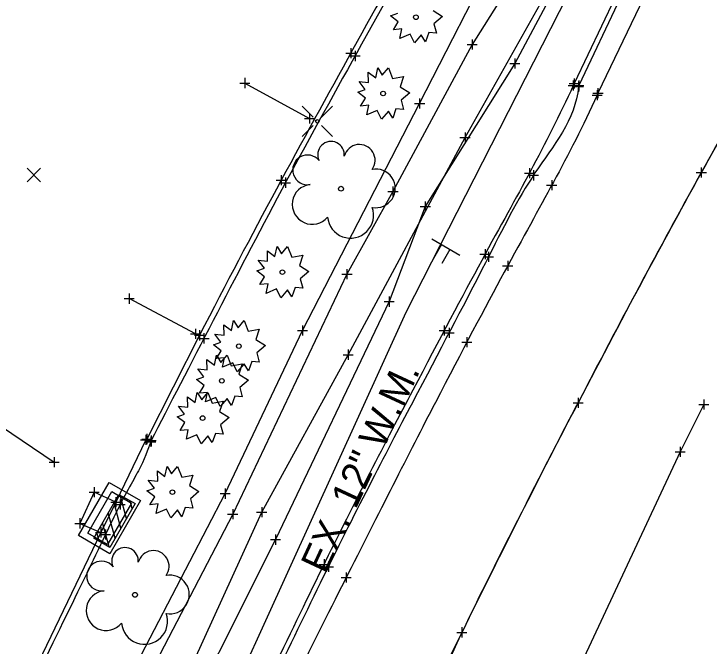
# Model space of a CAD drawing. Extents: x 1324089 to 1329959, y 459099 to 462017.
# Drawn here: x 1324763.5 to 1324832.3, y 459613.2 to 459675.8 of the extents above; entities that cross this region are included whole.
import ezdxf

# ---------------------------------------------------------------- set-up
doc = ezdxf.new("R2010")
doc.units = 0
for name, color, linetype in [('DR_X_Cells', 7, 'Continuous'), ('GK_Drainage_Nodes', 7, 'Continuous'), ('PM_X_Channelizing_Line', 7, 'Continuous'), ('PM_X_CL_Double_Solid', 7, 'Continuous'), ('PM_X_Parking_Lot_Stall', 7, 'Continuous'), ('PM_X_Surveyed_Line', 7, 'Continuous'), ('PV_X_Curb', 7, 'Continuous'), ('PV_X_EOP', 7, 'Continuous'), ('SN_X_Public', 7, 'Continuous'), ('SV_P_Control_Cells_Set', 7, 'Continuous'), ('SV_X_Break_Lines', 7, 'Continuous'), ('SV_X_Random_Point', 7, 'Continuous'), ('SV_X_Shot_Marker', 7, 'Continuous'), ('UT_X_Electric', 7, 'Continuous'), ('UT_X_Telecom', 7, 'Continuous'), ('UT_X_Water', 7, 'Continuous'), ('UT_X_Water_Text', 7, 'Continuous'), ('VG_X_Cells', 7, 'Continuous'), ('VG_X_Flower_Bed', 7, 'Continuous')]:
    doc.layers.add(name, color=color, linetype=linetype)

msp = doc.modelspace()

# ---------------------------------------------------------------- linework, layer by layer
at = {"layer": 'DR_X_Cells'}
for p, q in [((1324774.619, 459625.879), (1324773.998, 459628.183)), ((1324774.054, 459624.901), (1324773.381, 459627.401)), ((1324775.184, 459626.858), (1324774.979, 459627.617)), ((1324773.489, 459623.923), (1324772.816, 459626.423)), ((1324772.897, 459623.046), (1324772.251, 459625.444)), ((1324771.916, 459623.612), (1324771.686, 459624.466))]:
    msp.add_line(p, q, dxfattribs=at)
for points in [[(1324769.875, 459624.165), (1324772.917, 459629.433), (1324776.021, 459627.641), (1324772.979, 459622.373)], [(1324770.787, 459624.408), (1324773.162, 459628.522), (1324775.11, 459627.397), (1324772.735, 459623.283)], [(1324771.374, 459623.925), (1324773.874, 459628.255), (1324775.461, 459627.339), (1324772.961, 459623.008)]]:
    msp.add_lwpolyline(points, close=True, dxfattribs=at)
at = {"layer": 'GK_Drainage_Nodes'}
for p, q in [((1324774.136, 459627.96), (1324774.136, 459627.96)), ((1324771.397, 459626.799), (1324771.397, 459626.799)), ((1324771.974, 459626.465), (1324771.974, 459626.465)), ((1324772.624, 459626.09), (1324772.624, 459626.09)), ((1324772.624, 459626.09), (1324772.624, 459626.09)), ((1324772.948, 459625.903), (1324772.948, 459625.903)), ((1324773.923, 459625.34), (1324773.923, 459625.34)), ((1324774.5, 459625.007), (1324774.5, 459625.007)), ((1324771.761, 459623.846), (1324771.761, 459623.846))]:
    msp.add_line(p, q, dxfattribs=at)
at = {"layer": 'PM_X_Channelizing_Line'}
for p, q in [((1324831.798, 459637.163), (1324829.475, 459632.455)), ((1324829.475, 459632.455), (1324818.676, 459609.429))]:
    msp.add_line(p, q, dxfattribs=at)
for centre, radius, start, end in [((1325573.528, 459249.067), 848.223, 149.963008, 151.013497), ((1325513.668, 459282.23), 779.791, 151.013497, 151.826405), ((1326054.876, 458992.357), 1393.74, 151.826405, 152.434453), ((1325878.632, 459084.361), 1194.926, 152.434453, 153.153503), ((1325333.948, 459360.055), 584.444, 153.153503, 154.181664), ((1324858.545, 459590.062), 56.324, 154.18166, 155.38932), ((1344288.914, 450689.762), 21428.141, 155.389318, 155.4512321)]:
    msp.add_arc(centre, radius, start, end, dxfattribs=at)
at = {"layer": 'PM_X_CL_Double_Solid'}
msp.add_arc((1325531.441, 459274.948), 775.354, 153.934546, 154.866062, dxfattribs=at)
at = {"layer": 'PM_X_Parking_Lot_Stall'}
for p, q in [((1324786.344, 459668.982), (1324792.745, 459665.473)), ((1324781.461, 459644.15), (1324774.879, 459647.636))]:
    msp.add_line(p, q, dxfattribs=at)
at = {"layer": 'PM_X_Surveyed_Line'}
for p, q in [((1324831.798, 459637.163), (1324829.475, 459632.455)), ((1324829.475, 459632.455), (1324818.676, 459609.429))]:
    msp.add_line(p, q, dxfattribs=at)
for points in [[(1324786.344, 459668.982), (1324792.745, 459665.473)], [(1324781.461, 459644.15), (1324774.879, 459647.636)]]:
    msp.add_lwpolyline(points, dxfattribs=at)
for points in [[(1324902.004, 459768.599), (1324894.941, 459763.504), (1324888.122, 459746.257), (1324874.941, 459731.791), (1324865.637, 459716.437), (1324856.475, 459701.876), (1324843.996, 459681.95), (1324831.428, 459660.191), (1324819.333, 459637.476), (1324807.917, 459614.981), (1324797.326, 459592.73), (1324792.039, 459577.402), (1324788.306, 459570.294)], [(1324882.051, 459697.431), (1324879.878, 459695.477), (1324875.317, 459685.045), (1324863.849, 459669.9), (1324852.044, 459648.528), (1324840.309, 459626.835), (1324829.616, 459604.568), (1324819.173, 459582.508), (1324814.023, 459567.354), (1324810.553, 459560.343)], [(1324895.398, 459696.784), (1324891.217, 459693.874), (1324886.406, 459680.591), (1324874.119, 459663.845), (1324862.634, 459642.513), (1324851.351, 459621.014), (1324840.499, 459599.29), (1324829.569, 459576.032), (1324822.647, 459560.039), (1324819.018, 459551.27)]]:
    msp.add_open_spline(points, degree=3, dxfattribs=at)
at = {"layer": 'PV_X_Curb'}
for p, q in [((1324829.782, 459691.74), (1324818.975, 459668.938)), ((1324830.176, 459691.43), (1324819.412, 459668.743)), ((1324818.975, 459668.938), (1324818.877, 459668.729)), ((1324819.412, 459668.743), (1324819.401, 459668.627))]:
    msp.add_line(p, q, dxfattribs=at)
for points in [[(1324817.796, 459706.566), (1324815.952, 459703.677), (1324811.609, 459696.727), (1324804.78, 459685.077), (1324797.497, 459672.141), (1324789.824, 459658.239), (1324783.217, 459645.473), (1324778.794, 459636.954), (1324777.054, 459633.576)], [(1324818.877, 459668.729), (1324817.51, 459665.803), (1324814.677, 459660.19), (1324810.196, 459652.226), (1324803.358, 459639.344), (1324794.246, 459621.807), (1324783.589, 459599.084), (1324776.054, 459584.39), (1324773.333, 459576.628)], [(1324819.401, 459668.627), (1324819.105, 459665.356), (1324814.629, 459660.122), (1324810.65, 459651.989), (1324803.829, 459639.044), (1324794.695, 459621.586), (1324783.937, 459598.887), (1324776.771, 459584.078), (1324773.747, 459576.435)], [(1324777.054, 459633.576), (1324777.041, 459633.536), (1324776.327, 459631.307), (1324774.445, 459628.358), (1324770.667, 459620.305), (1324767.716, 459614.392), (1324765.326, 459609.444)]]:
    msp.add_open_spline(points, degree=3, dxfattribs=at)
at = {"layer": 'PV_X_EOP'}
for p, q in [((1324832.047, 459690.408), (1324821.323, 459667.983)), ((1324821.323, 459667.983), (1324821.233, 459667.781)), ((1324781.846, 459644.003), (1324776.628, 459633.733)), ((1324776.519, 459633.645), (1324773.569, 459627.484)), ((1324776.628, 459633.733), (1324776.519, 459633.645)), ((1324773.569, 459627.484), (1324772.064, 459624.492)), ((1324772.064, 459624.492), (1324764.934, 459609.672))]:
    msp.add_line(p, q, dxfattribs=at)
for points in [[(1324817.184, 459706.405), (1324815.465, 459703.707), (1324811.035, 459696.861), (1324804.312, 459685.413), (1324797.096, 459672.405), (1324789.428, 459658.502), (1324784.502, 459649.145), (1324781.846, 459644.003)], [(1324821.233, 459667.781), (1324819.873, 459664.74), (1324816.914, 459659.104), (1324812.44, 459651.05), (1324805.564, 459638.152), (1324796.645, 459620.538), (1324785.298, 459598.094), (1324779.342, 459582.724), (1324775.523, 459575.408)]]:
    msp.add_open_spline(points, degree=3, dxfattribs=at)
at = {"layer": 'SN_X_Public'}
for p, q in [((1324804.862, 459653.542), (1324807.633, 459651.942)), ((1324805.832, 459652.982), (1324805.032, 459651.597)), ((1324806.663, 459652.502), (1324805.863, 459651.117)), ((1324806.247, 459652.742), (1324806.247, 459652.742))]:
    msp.add_line(p, q, dxfattribs=at)
at = {"layer": 'SV_P_Control_Cells_Set'}
for p, q in [((1324793.112, 459665.607), (1324792.019, 459666.699)), ((1324793.944, 459665.607), (1324795.037, 459666.699)), ((1324792.019, 459663.68), (1324793.112, 459664.774)), ((1324795.037, 459663.68), (1324793.944, 459664.774))]:
    msp.add_line(p, q, dxfattribs=at)
msp.add_circle((1324793.522, 459665.19), 0.17, dxfattribs=at)
at = {"layer": 'SV_X_Break_Lines'}
for points in [[(1324830.664, 459710.011), (1324831.232, 459705.696), (1324825.964, 459694.744), (1324819.943, 459683.777), (1324813.087, 459670.907), (1324804.221, 459656.761), (1324800.65, 459647.335), (1324789.388, 459623.769), (1324778.115, 459601.349)], [(1324754.738, 459640.021), (1324767.463, 459631.432)], [(1324773.569, 459627.484), (1324771.424, 459628.467), (1324770.012, 459625.385), (1324772.064, 459624.492)]]:
    msp.add_lwpolyline(points, dxfattribs=at)
at = {"layer": 'SV_X_Random_Point'}
for p, q in [((1324764.772, 459659.205), (1324766.105, 459660.54)), ((1324764.772, 459660.54), (1324766.105, 459659.205))]:
    msp.add_line(p, q, dxfattribs=at)
at = {"layer": 'SV_X_Shot_Marker'}
for p, q in [((1324808.867, 459673.303), (1324808.867, 459672.303)), ((1324796.851, 459672.449), (1324796.851, 459671.449)), ((1324797.254, 459672.162), (1324797.254, 459671.162)), ((1324808.367, 459672.803), (1324809.367, 459672.803)), ((1324808.867, 459672.803), (1324808.867, 459672.803)), ((1324796.351, 459671.949), (1324797.351, 459671.949)), ((1324796.754, 459671.662), (1324797.754, 459671.662)), ((1324796.851, 459671.949), (1324796.851, 459671.949)), ((1324797.254, 459671.662), (1324797.254, 459671.662)), ((1324812.587, 459670.907), (1324813.587, 459670.907)), ((1324813.087, 459671.407), (1324813.087, 459670.407)), ((1324813.087, 459670.907), (1324813.087, 459670.907)), ((1324786.344, 459669.482), (1324786.344, 459668.482)), ((1324818.975, 459669.438), (1324818.975, 459668.438)), ((1324785.844, 459668.982), (1324786.844, 459668.982)), ((1324786.344, 459668.982), (1324786.344, 459668.982)), ((1324818.377, 459668.729), (1324819.377, 459668.729)), ((1324818.475, 459668.938), (1324819.475, 459668.938)), ((1324818.877, 459669.229), (1324818.877, 459668.229)), ((1324818.877, 459668.729), (1324818.877, 459668.729)), ((1324818.912, 459668.743), (1324819.912, 459668.743)), ((1324818.975, 459668.938), (1324818.975, 459668.938)), ((1324819.401, 459669.127), (1324819.401, 459668.127)), ((1324819.412, 459669.243), (1324819.412, 459668.243)), ((1324819.412, 459668.743), (1324819.412, 459668.743)), ((1324818.901, 459668.627), (1324819.901, 459668.627)), ((1324819.401, 459668.627), (1324819.401, 459668.627)), ((1324821.233, 459668.281), (1324821.233, 459667.281)), ((1324821.323, 459668.483), (1324821.323, 459667.483)), ((1324803.656, 459667.451), (1324803.656, 459666.451)), ((1324820.733, 459667.781), (1324821.733, 459667.781)), ((1324820.823, 459667.983), (1324821.823, 459667.983)), ((1324821.233, 459667.781), (1324821.233, 459667.781)), ((1324821.323, 459667.983), (1324821.323, 459667.983)), ((1324803.156, 459666.951), (1324804.156, 459666.951)), ((1324803.656, 459666.951), (1324803.656, 459666.951)), ((1324792.745, 459665.973), (1324792.745, 459664.973)), ((1324792.245, 459665.473), (1324793.245, 459665.473)), ((1324792.745, 459665.473), (1324792.745, 459665.473)), ((1324808.155, 459664.074), (1324808.155, 459663.074)), ((1324807.655, 459663.574), (1324808.655, 459663.574)), ((1324808.155, 459663.574), (1324808.155, 459663.574)), ((1324814.531, 459660.567), (1324814.531, 459659.567)), ((1324831.558, 459660.619), (1324831.558, 459659.619)), ((1324789.948, 459659.856), (1324789.948, 459658.856)), ((1324814.031, 459660.067), (1324815.031, 459660.067)), ((1324814.442, 459659.845), (1324815.442, 459659.845)), ((1324814.531, 459660.067), (1324814.531, 459660.067)), ((1324814.942, 459660.345), (1324814.942, 459659.345)), ((1324814.942, 459659.845), (1324814.942, 459659.845)), ((1324831.058, 459660.119), (1324832.058, 459660.119)), ((1324831.558, 459660.119), (1324831.558, 459660.119)), ((1324789.448, 459659.356), (1324790.448, 459659.356)), ((1324789.872, 459659.113), (1324790.872, 459659.113)), ((1324789.948, 459659.356), (1324789.948, 459659.356)), ((1324790.372, 459659.613), (1324790.372, 459658.613)), ((1324790.372, 459659.113), (1324790.372, 459659.113)), ((1324816.739, 459659.36), (1324816.739, 459658.36)), ((1324801.014, 459658.752), (1324801.014, 459657.752)), ((1324816.239, 459658.86), (1324817.239, 459658.86)), ((1324816.739, 459658.86), (1324816.739, 459658.86)), ((1324800.514, 459658.252), (1324801.514, 459658.252)), ((1324801.014, 459658.252), (1324801.014, 459658.252)), ((1324804.221, 459657.261), (1324804.221, 459656.261)), ((1324803.721, 459656.761), (1324804.721, 459656.761)), ((1324804.221, 459656.761), (1324804.221, 459656.761)), ((1324810.133, 459652.536), (1324810.133, 459651.536)), ((1324810.487, 459652.265), (1324810.487, 459651.265)), ((1324809.633, 459652.036), (1324810.633, 459652.036)), ((1324809.987, 459651.765), (1324810.987, 459651.765)), ((1324810.133, 459652.036), (1324810.133, 459652.036)), ((1324810.487, 459651.765), (1324810.487, 459651.765)), ((1324811.879, 459650.885), (1324812.879, 459650.885)), ((1324812.379, 459651.385), (1324812.379, 459650.385)), ((1324812.379, 459650.885), (1324812.379, 459650.885)), ((1324796.461, 459650.561), (1324796.461, 459649.561)), ((1324795.961, 459650.061), (1324796.961, 459650.061)), ((1324796.461, 459650.061), (1324796.461, 459650.061)), ((1324774.879, 459648.136), (1324774.879, 459647.136)), ((1324774.379, 459647.636), (1324775.379, 459647.636)), ((1324774.879, 459647.636), (1324774.879, 459647.636)), ((1324800.65, 459647.835), (1324800.65, 459646.835)), ((1324800.15, 459647.335), (1324801.15, 459647.335)), ((1324800.65, 459647.335), (1324800.65, 459647.335)), ((1324781.461, 459644.65), (1324781.461, 459643.65)), ((1324792.042, 459644.978), (1324792.042, 459643.978)), ((1324806.093, 459644.984), (1324806.093, 459643.984)), ((1324806.571, 459644.743), (1324806.571, 459643.743)), ((1324780.961, 459644.15), (1324781.961, 459644.15)), ((1324781.346, 459644.003), (1324782.346, 459644.003)), ((1324781.461, 459644.15), (1324781.461, 459644.15)), ((1324781.846, 459644.503), (1324781.846, 459643.503)), ((1324781.846, 459644.003), (1324781.846, 459644.003)), ((1324782.294, 459644.201), (1324782.294, 459643.201)), ((1324791.542, 459644.478), (1324792.542, 459644.478)), ((1324792.042, 459644.478), (1324792.042, 459644.478)), ((1324805.593, 459644.484), (1324806.593, 459644.484)), ((1324806.071, 459644.243), (1324807.071, 459644.243)), ((1324806.093, 459644.484), (1324806.093, 459644.484)), ((1324806.571, 459644.243), (1324806.571, 459644.243)), ((1324781.794, 459643.701), (1324782.794, 459643.701)), ((1324782.294, 459643.701), (1324782.294, 459643.701)), ((1324807.84, 459643.329), (1324808.84, 459643.329)), ((1324808.34, 459643.829), (1324808.34, 459642.829)), ((1324808.34, 459643.329), (1324808.34, 459643.329)), ((1324796.566, 459642.584), (1324796.566, 459641.584)), ((1324796.066, 459642.084), (1324797.066, 459642.084)), ((1324796.566, 459642.084), (1324796.566, 459642.084)), ((1324819.351, 459637.828), (1324819.351, 459636.828)), ((1324818.851, 459637.328), (1324819.851, 459637.328)), ((1324819.351, 459637.328), (1324819.351, 459637.328)), ((1324831.298, 459637.163), (1324832.298, 459637.163)), ((1324831.798, 459637.663), (1324831.798, 459636.663)), ((1324831.798, 459637.163), (1324831.798, 459637.163)), ((1324776.019, 459633.645), (1324777.019, 459633.645)), ((1324776.128, 459633.733), (1324777.128, 459633.733)), ((1324776.519, 459634.145), (1324776.519, 459633.145)), ((1324776.519, 459633.645), (1324776.519, 459633.645)), ((1324776.554, 459633.576), (1324777.554, 459633.576)), ((1324776.628, 459634.233), (1324776.628, 459633.233)), ((1324776.628, 459633.733), (1324776.628, 459633.733)), ((1324777.015, 459633.956), (1324777.015, 459632.956)), ((1324777.054, 459634.076), (1324777.054, 459633.076)), ((1324777.054, 459633.576), (1324777.054, 459633.576)), ((1324776.515, 459633.456), (1324777.515, 459633.456)), ((1324777.015, 459633.456), (1324777.015, 459633.456)), ((1324829.475, 459632.955), (1324829.475, 459631.955)), ((1324828.975, 459632.455), (1324829.975, 459632.455)), ((1324829.475, 459632.455), (1324829.475, 459632.455)), ((1324767.463, 459631.932), (1324767.463, 459630.932)), ((1324766.963, 459631.432), (1324767.963, 459631.432)), ((1324767.463, 459631.432), (1324767.463, 459631.432)), ((1324771.424, 459628.967), (1324771.424, 459627.967)), ((1324784.385, 459628.824), (1324784.385, 459627.824)), ((1324770.924, 459628.467), (1324771.924, 459628.467)), ((1324771.424, 459628.467), (1324771.424, 459628.467)), ((1324783.885, 459628.324), (1324784.885, 459628.324)), ((1324784.385, 459628.324), (1324784.385, 459628.324)), ((1324773.069, 459627.484), (1324774.069, 459627.484)), ((1324773.069, 459627.484), (1324774.069, 459627.484)), ((1324773.569, 459627.984), (1324773.569, 459626.984)), ((1324773.569, 459627.984), (1324773.569, 459626.984)), ((1324773.569, 459627.484), (1324773.569, 459627.484)), ((1324773.569, 459627.484), (1324773.569, 459627.484)), ((1324773.982, 459627.761), (1324773.982, 459626.761)), ((1324773.482, 459627.261), (1324774.482, 459627.261)), ((1324773.982, 459627.261), (1324773.982, 459627.261)), ((1324785.136, 459626.801), (1324785.136, 459625.801)), ((1324788.009, 459627.003), (1324788.009, 459626.003)), ((1324784.636, 459626.301), (1324785.636, 459626.301)), ((1324785.136, 459626.301), (1324785.136, 459626.301)), ((1324787.509, 459626.503), (1324788.509, 459626.503)), ((1324788.009, 459626.503), (1324788.009, 459626.503)), ((1324769.512, 459625.385), (1324770.512, 459625.385)), ((1324770.012, 459625.885), (1324770.012, 459624.885)), ((1324770.012, 459625.385), (1324770.012, 459625.385)), ((1324772.064, 459624.992), (1324772.064, 459623.992)), ((1324772.064, 459624.992), (1324772.064, 459623.992)), ((1324772.525, 459624.776), (1324772.525, 459623.776)), ((1324771.564, 459624.492), (1324772.564, 459624.492)), ((1324771.564, 459624.492), (1324772.564, 459624.492)), ((1324772.025, 459624.276), (1324773.025, 459624.276)), ((1324772.064, 459624.492), (1324772.064, 459624.492)), ((1324772.064, 459624.492), (1324772.064, 459624.492)), ((1324772.525, 459624.276), (1324772.525, 459624.276)), ((1324789.388, 459624.269), (1324789.388, 459623.269)), ((1324788.888, 459623.769), (1324789.888, 459623.769)), ((1324789.388, 459623.769), (1324789.388, 459623.769)), ((1324793.7, 459621.326), (1324794.7, 459621.326)), ((1324794.2, 459621.826), (1324794.2, 459620.826)), ((1324794.2, 459621.326), (1324794.2, 459621.326)), ((1324794.635, 459621.591), (1324794.635, 459620.591)), ((1324794.135, 459621.091), (1324795.135, 459621.091)), ((1324794.635, 459621.091), (1324794.635, 459621.091)), ((1324796.389, 459620.527), (1324796.389, 459619.527)), ((1324795.889, 459620.027), (1324796.889, 459620.027)), ((1324796.389, 459620.027), (1324796.389, 459620.027)), ((1324807.843, 459615.092), (1324807.843, 459614.092)), ((1324807.343, 459614.592), (1324808.343, 459614.592)), ((1324807.843, 459614.592), (1324807.843, 459614.592))]:
    msp.add_line(p, q, dxfattribs=at)
at = {"layer": 'UT_X_Electric'}
msp.add_lwpolyline([(1324693.778, 459434.478), (1324728.417, 459505.081), (1324734.193, 459518.283), (1324737.487, 459522.829), (1324744.918, 459527.329), (1324746.416, 459531.379), (1324752.749, 459551.702), (1324758.48, 459559.617), (1324763.392, 459566.917), (1324767.702, 459575.371), (1324770.006, 459583.024), (1324772.576, 459592.111), (1324780.33, 459609.613), (1324788.009, 459626.503), (1324796.566, 459642.084), (1324808.155, 459663.574), (1324817.983, 459681.056), (1324824.851, 459693.877), (1324829.454, 459705.711), (1324832.056, 459714.352), (1324831.327, 459723.942), (1324829.429, 459731.63), (1324825.372, 459738.259), (1324821.702, 459744.731)], dxfattribs=at)
at = {"layer": 'UT_X_Telecom'}
msp.add_lwpolyline([(1324698.774, 459420.103), (1324700.908, 459427.07), (1324737.481, 459515.821), (1324737.413, 459516.046), (1324738.823, 459521.946), (1324747.971, 459550.794), (1324751.859, 459563.444), (1324759.06, 459579.949), (1324766.885, 459595.14), (1324775.632, 459611.505), (1324784.385, 459628.324), (1324792.042, 459644.478), (1324803.656, 459666.951), (1324811.534, 459682.366), (1324815.201, 459692.638), (1324816.714, 459699.252), (1324819.158, 459705.836), (1324820.469, 459711.84), (1324822.074, 459721.286), (1324822.102, 459726.693), (1324822.023, 459731.99), (1324820.97, 459738.064), (1324819.837, 459744.289)], dxfattribs=at)
at = {"layer": 'UT_X_Water'}
msp.add_lwpolyline([(1324683.283, 459219.357), (1324691.61, 459298.587), (1324698.63, 459347.922), (1324699.63, 459354.943), (1324721.275, 459442.344), (1324756.062, 459540.186), (1324772.185, 459580.087), (1324802.339, 459646.278), (1324825.104, 459690.992), (1324841.263, 459722.731), (1324902.17, 459810.082), (1324917.22, 459828.862)], dxfattribs=at)
at = {"layer": 'VG_X_Cells'}
for points in [[(1324804.982, 459676.16), (1324805.927, 459675.565), (1324805.07, 459674.83), (1324805.32, 459673.917), (1324804.567, 459673.985), (1324804.242, 459673.072), (1324803.814, 459673.764), (1324803.135, 459672.947), (1324802.707, 459673.834), (1324801.687, 459673.404), (1324801.879, 459674.345), (1324801.067, 459674.262), (1324801.54, 459675.052), (1324800.772, 459675.62), (1324801.51, 459675.884)], [(1324799.957, 459669.753), (1324800.562, 459670.488), (1324800.977, 459669.434), (1324802.069, 459669.614), (1324801.73, 459668.603), (1324802.675, 459668.008), (1324801.819, 459667.273), (1324802.069, 459666.359), (1324801.315, 459666.428), (1324800.99, 459665.514), (1324800.562, 459666.206), (1324799.884, 459665.389), (1324799.455, 459666.276), (1324798.435, 459665.846), (1324798.627, 459666.788), (1324797.815, 459666.704), (1324798.289, 459667.494), (1324797.52, 459668.063), (1324798.259, 459668.326), (1324797.652, 459669.129), (1324798.584, 459669.019), (1324798.554, 459670.058), (1324799.307, 459669.489), (1324799.514, 459670.474), (1324799.957, 459669.753)], [(1324789.974, 459652.066), (1324790.579, 459652.801), (1324790.994, 459651.748), (1324792.085, 459651.928), (1324791.747, 459650.916), (1324792.692, 459650.321), (1324791.835, 459649.586), (1324792.085, 459648.673), (1324791.332, 459648.741), (1324791.007, 459647.828), (1324790.579, 459648.519), (1324789.9, 459647.703), (1324789.472, 459648.589), (1324788.452, 459648.159), (1324788.644, 459649.101), (1324787.832, 459649.018), (1324788.305, 459649.808), (1324787.537, 459650.376), (1324788.275, 459650.639), (1324787.669, 459651.443), (1324788.6, 459651.333), (1324788.57, 459652.371), (1324789.324, 459651.803), (1324789.53, 459652.788), (1324789.974, 459652.066)], [(1324785.665, 459644.74), (1324786.27, 459645.475), (1324786.685, 459644.422), (1324787.776, 459644.602), (1324787.438, 459643.59), (1324788.383, 459642.995), (1324787.526, 459642.26), (1324787.776, 459641.347), (1324787.023, 459641.415), (1324786.698, 459640.502), (1324786.27, 459641.193), (1324785.591, 459640.377), (1324785.163, 459641.263), (1324784.143, 459640.833), (1324784.335, 459641.775), (1324783.523, 459641.692), (1324783.996, 459642.482), (1324783.228, 459643.05), (1324783.966, 459643.313), (1324783.36, 459644.117), (1324784.291, 459644.007), (1324784.261, 459645.045), (1324785.015, 459644.477), (1324785.221, 459645.462), (1324785.665, 459644.74)], [(1324783.977, 459641.307), (1324784.582, 459642.042), (1324784.997, 459640.989), (1324786.089, 459641.169), (1324785.75, 459640.157), (1324786.695, 459639.562), (1324785.839, 459638.827), (1324786.089, 459637.914), (1324785.335, 459637.982), (1324785.01, 459637.069), (1324784.582, 459637.761), (1324783.904, 459636.944), (1324783.475, 459637.831), (1324782.455, 459637.401), (1324782.647, 459638.342), (1324781.835, 459638.259), (1324782.309, 459639.049), (1324781.54, 459639.617), (1324782.279, 459639.881), (1324781.672, 459640.684), (1324782.604, 459640.574), (1324782.574, 459641.612), (1324783.327, 459641.044), (1324783.534, 459642.029), (1324783.977, 459641.307)], [(1324782.073, 459637.613), (1324782.678, 459638.348), (1324783.093, 459637.295), (1324784.184, 459637.475), (1324783.846, 459636.463), (1324784.791, 459635.868), (1324783.934, 459635.133), (1324784.184, 459634.22), (1324783.431, 459634.288), (1324783.106, 459633.375), (1324782.678, 459634.066), (1324781.999, 459633.25), (1324781.571, 459634.136), (1324780.551, 459633.706), (1324780.743, 459634.648), (1324779.931, 459634.565), (1324780.404, 459635.355), (1324779.636, 459635.923), (1324780.374, 459636.186), (1324779.768, 459636.99), (1324780.699, 459636.88), (1324780.669, 459637.918), (1324781.423, 459637.35), (1324781.629, 459638.335), (1324782.073, 459637.613)], [(1324779.08, 459630.282), (1324779.685, 459631.017), (1324780.1, 459629.963), (1324781.192, 459630.143), (1324780.854, 459629.132), (1324781.799, 459628.537), (1324780.942, 459627.802), (1324781.192, 459626.888), (1324780.439, 459626.957), (1324780.114, 459626.043), (1324779.685, 459626.735), (1324779.007, 459625.918), (1324778.579, 459626.805), (1324777.559, 459626.375), (1324777.75, 459627.317), (1324776.939, 459627.233), (1324777.412, 459628.023), (1324776.644, 459628.592), (1324777.382, 459628.855), (1324776.775, 459629.658), (1324777.707, 459629.548), (1324777.677, 459630.587), (1324778.431, 459630.018), (1324778.637, 459631.003), (1324779.08, 459630.282)]]:
    msp.add_lwpolyline(points, dxfattribs=at)
for centre, radius in [((1324803.293, 459675.501), 0.23), ((1324800.041, 459667.943), 0.23), ((1324795.865, 459658.515), 0.24), ((1324790.058, 459650.256), 0.23), ((1324785.749, 459642.93), 0.23), ((1324784.061, 459639.498), 0.23), ((1324782.157, 459635.803), 0.23), ((1324779.165, 459628.472), 0.23), ((1324775.458, 459618.302), 0.24)]:
    msp.add_circle(centre, radius, dxfattribs=at)
for centre, radius, start, end in [((1324794.881, 459661.882), 1.317, 354.0047, 205.97412), ((1324797.691, 459661.344), 1.553, 323.82996, 165.0376), ((1324792.556, 459660.379), 1.471, 39.06254, 279.54124), ((1324799.325, 459658.551), 1.915, 259.14531, 101.45961), ((1324793.012, 459656.966), 1.974, 96.17219, 320.57371), ((1324796.812, 459655.909), 2.284, 184.94757, 19.45715), ((1324774.474, 459621.669), 1.317, 354.0047, 205.97412), ((1324777.284, 459621.131), 1.553, 323.82996, 165.0376), ((1324772.148, 459620.166), 1.471, 39.06254, 279.54124), ((1324778.918, 459618.338), 1.915, 259.14531, 101.45961), ((1324772.604, 459616.753), 1.974, 96.17219, 320.57371), ((1324776.404, 459615.696), 2.284, 184.94757, 19.45715)]:
    msp.add_arc(centre, radius, start, end, dxfattribs=at)
at = {"layer": 'VG_X_Flower_Bed'}
for p, q in [((1324823.374, 459695.783), (1324808.867, 459672.803)), ((1324808.867, 459672.803), (1324801.014, 459658.252)), ((1324801.014, 459658.252), (1324796.461, 459650.061)), ((1324796.461, 459650.061), (1324785.136, 459626.301)), ((1324785.136, 459626.301), (1324773.379, 459603.722))]:
    msp.add_line(p, q, dxfattribs=at)

# ---------------------------------------------------------------- texts
at = {"layer": 'UT_X_Water_Text'}
msp.add_text('EX. 12" W.M.', height=2.8, rotation=65.05875, dxfattribs=at).set_placement((1324794.329, 459620.276))

doc.saveas('drawing.dxf')
